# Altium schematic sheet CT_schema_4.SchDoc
size 294 x 169 mm
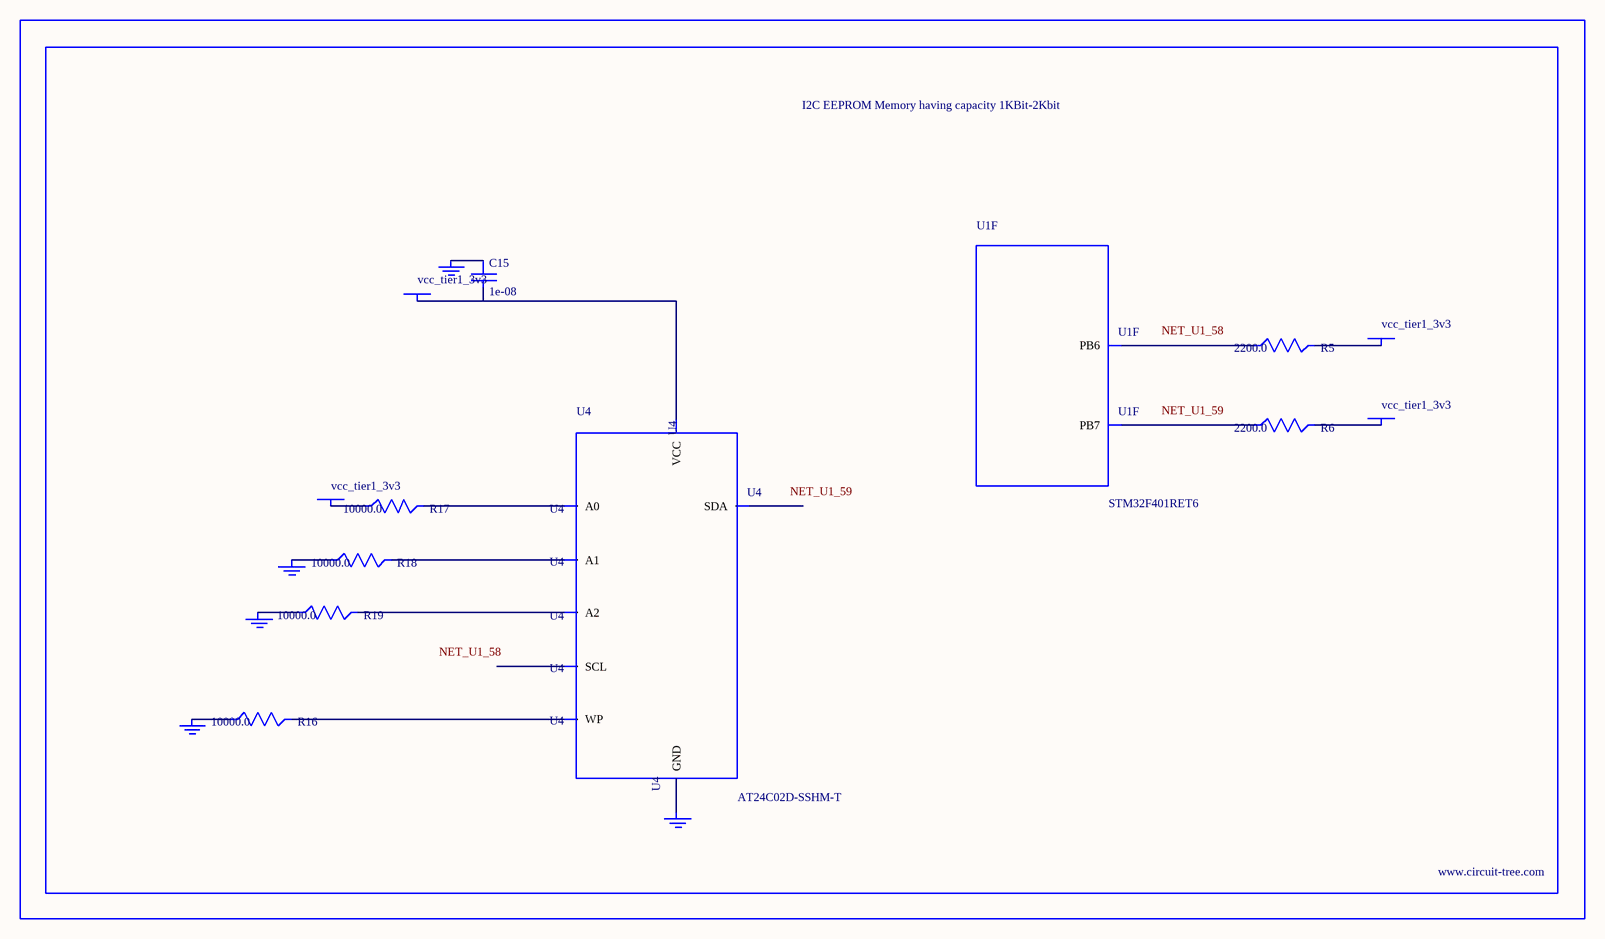
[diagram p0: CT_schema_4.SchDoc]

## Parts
BORDER3  (no value)
C15  1e-08  [C0402]
GND_INSTANCE_3_0  (no value)
GND_INSTANCE_3_1  (no value)
GND_INSTANCE_3_2  (no value)
GND_INSTANCE_3_3  (no value)
GND_INSTANCE_3_4  (no value)
POWER_INSTANCE_3_0  vcc_tier1_3v3
POWER_INSTANCE_3_1  vcc_tier1_3v3
POWER_INSTANCE_3_2  vcc_tier1_3v3
POWER_INSTANCE_3_3  vcc_tier1_3v3
R5  2200.0  [R0603]
R6  2200.0  [R0603]
R16  10000.0  [R0603]
R17  10000.0  [R0603]
R18  10000.0  [R0603]
R19  10000.0  [R0603]
U1  STM32F401RET6  [LQFP64]  (part F of 7)
U4  AT24C02D-SSHM-T  [AT24C02D]

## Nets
NetC15_1: C15.1 GND_INSTANCE_3_3.0(GND)
NetC15_2: C15.2 POWER_INSTANCE_3_1.0(PWR) U4.8(VCC)
NetGND_INSTANCE_3_0_0: GND_INSTANCE_3_0.0(GND) R18.1
NetGND_INSTANCE_3_1_0: GND_INSTANCE_3_1.0(GND) R19.1
NetGND_INSTANCE_3_2_0: GND_INSTANCE_3_2.0(GND) R16.1
NetGND_INSTANCE_3_4_0: GND_INSTANCE_3_4.0(GND) U4.4(GND)
NetPOWER_INSTANCE_3_0_0: POWER_INSTANCE_3_0.0(PWR) R17.1
NetPOWER_INSTANCE_3_2_0: POWER_INSTANCE_3_2.0(PWR) R5.2
NetPOWER_INSTANCE_3_3_0: POWER_INSTANCE_3_3.0(PWR) R6.2
NetR5_1: R5.1 U1.58(PB6)
NetR6_1: R6.1 U1.59(PB7)
NetR16_2: R16.2 U4.7(WP)
NetR17_2: R17.2 U4.1(A0)
NetR18_2: R18.2 U4.2(A1)
NetR19_2: R19.2 U4.3(A2)

Not connected (* = marked no-connect by the designer): U4 5(SDA) 6(SCL)

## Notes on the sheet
- Labels drawn without touching a wire or pin: NET_U1_58, NET_U1_59

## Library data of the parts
BORDER3 = BORDER_PAGE3
C15 = C0402C103K3RAC
GND_INSTANCE_3_0-GND_INSTANCE_3_4 = GND
POWER_INSTANCE_3_0-POWER_INSTANCE_3_3 = PWR
R5 R6 = RC0603JR-072K2L
R16-R19 = RC0603JR-0710KL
